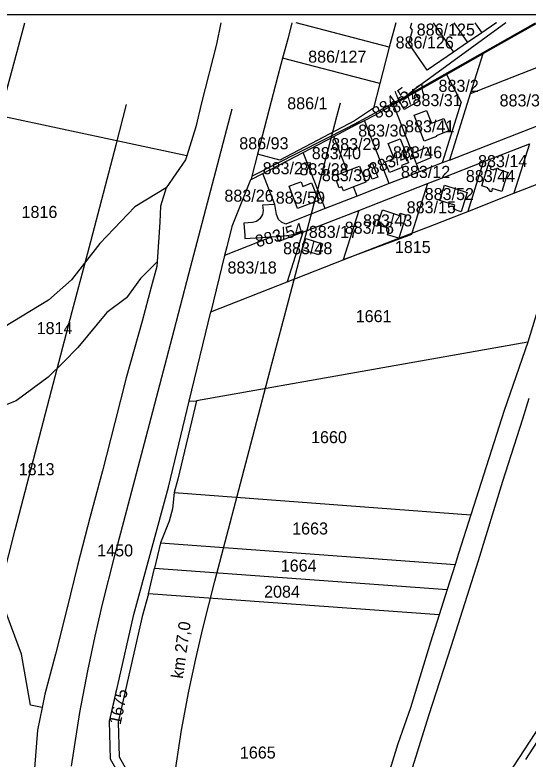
# Model space of a CAD drawing. Extents: x -583889 to -582839, y -1166553 to -1165068.
# Drawn here: x -583410.2 to -583111.8, y -1165500.8 to -1165067.8 of the extents above; entities that cross this region are included whole.
import ezdxf

# ---------------------------------------------------------------- set-up
doc = ezdxf.new("R2010")
doc.units = 0
for name, color, linetype in [('37', 7, 'Continuous'), ('_parcely přehledka', 7, 'Continuous'), ('Hranice parcel', 7, 'Continuous'), ('Parcelní čísla', 7, 'Continuous')]:
    doc.layers.add(name, color=color, linetype=linetype)

msp = doc.modelspace()

# ---------------------------------------------------------------- linework, layer by layer
at = {"layer": '37'}
for points in [[(-583417.44, -1165396.54), (-583410.09, -1165367.4), (-583389.99, -1165290.81), (-583376.8, -1165240.45), (-583367.04, -1165203.24), (-583351.37, -1165143.48), (-583345.2, -1165119.98)], [(-583317.86, -1165513.43), (-583313.23, -1165483.92), (-583308.97, -1165461.26), (-583304.95, -1165442.46), (-583300.84, -1165424.92), (-583293.87, -1165397.32), (-583273.91, -1165321.23), (-583260.72, -1165270.87), (-583250.96, -1165233.68), (-583235.29, -1165173.92), (-583222.96, -1165126.91), (-583220.86, -1165118.88)], [(-583377.27, -1165504.99), (-583372.36, -1165473.73), (-583367.8, -1165449.45), (-583363.5, -1165429.34), (-583359.14, -1165410.73), (-583351.98, -1165382.36), (-583344.08, -1165352.25), (-583331.95, -1165306.02), (-583318.76, -1165255.66), (-583309, -1165218.46), (-583293.33, -1165158.7), (-583283.82, -1165122.45)]]:
    msp.add_lwpolyline(points, dxfattribs=at)
at = {"layer": '_parcely přehledka'}
msp.add_lwpolyline([(-583888.67, -1166552.78), (-582838.67, -1166552.78), (-582838.67, -1165067.78), (-583888.67, -1165067.78), (-583888.67, -1166552.78)], dxfattribs=at)
at = {"layer": 'Hranice parcel'}
for p, q in [((-583192.52, -1165086.48), (-583246.64, -1165072.33)), ((-583188.82, -1165072.33), (-583192.52, -1165086.48)), ((-583182.09, -1165114.62), (-583107.53, -1165072.33)), ((-583167.06, -1165072.33), (-583155.29, -1165089.5)), ((-583154.94, -1165072.33), (-583147.04, -1165083.85)), ((-583142.81, -1165072.33), (-583138.79, -1165078.2)), ((-583130.54, -1165072.55), (-583138.79, -1165078.2)), ((-583106.15, -1165072.33), (-583138.25, -1165090.53)), ((-583130.69, -1165072.33), (-583130.54, -1165072.55)), ((-583130.22, -1165072.33), (-583130.54, -1165072.55)), ((-583138.79, -1165078.2), (-583147.04, -1165083.85)), ((-583060.04, -1165080.27), (-583145.52, -1165113.73)), ((-583147.04, -1165083.85), (-583155.29, -1165089.5)), ((-583192.52, -1165086.48), (-583198.08, -1165107.77)), ((-583198.08, -1165107.77), (-583254.56, -1165093)), ((-583159.2, -1165102.41), (-583138.25, -1165090.53)), ((-583138.25, -1165090.53), (-583145.52, -1165113.73)), ((-583177.74, -1165112.93), (-583159.2, -1165102.41)), ((-583209.97, -1165129.86), (-583182.09, -1165114.62)), ((-583185.39, -1165117.27), (-583177.74, -1165112.93)), ((-583182.09, -1165114.62), (-583185.39, -1165117.27)), ((-583145.52, -1165113.73), (-583157.61, -1165152.25)), ((-583190.15, -1165119.97), (-583186.69, -1165118.01)), ((-583179.13, -1165148.17), (-583190.15, -1165119.97)), ((-583186.69, -1165118.01), (-583185.39, -1165117.27)), ((-583157.61, -1165152.25), (-583071.94, -1165118.73)), ((-583310.2, -1165149.72), (-583419.03, -1165126.58)), ((-583213.82, -1165132.82), (-583206.95, -1165129.23)), ((-583192.59, -1165165.93), (-583206.95, -1165129.23)), ((-583224.78, -1165138.54), (-583213.82, -1165132.82)), ((-583213.82, -1165132.82), (-583209.97, -1165129.86)), ((-583242.61, -1165147.85), (-583224.78, -1165138.54)), ((-583216.94, -1165158.58), (-583224.78, -1165138.54)), ((-583137.89, -1165153.24), (-583111.02, -1165142.73)), ((-583111.02, -1165142.73), (-583120.08, -1165171.59)), ((-583269.11, -1165148.86), (-583272.42, -1165161.67)), ((-583266.01, -1165160.07), (-583242.61, -1165147.85)), ((-583229.84, -1165180.5), (-583242.61, -1165147.85)), ((-583176.72, -1165154.36), (-583179.13, -1165148.17)), ((-583174.9, -1165159.01), (-583176.72, -1165154.36)), ((-583161.79, -1165153.89), (-583174.9, -1165159.01)), ((-583157.61, -1165152.25), (-583161.79, -1165153.89)), ((-583137.89, -1165153.24), (-583146.95, -1165182.1)), ((-583174.9, -1165159.01), (-583192.59, -1165165.93)), ((-583120.08, -1165171.59), (-583084.11, -1165157.51)), ((-583273.25, -1165163.85), (-583266.01, -1165160.07)), ((-583258.98, -1165178.07), (-583266.01, -1165160.07)), ((-583211.22, -1165173.22), (-583213.34, -1165167.8)), ((-583192.59, -1165165.93), (-583211.22, -1165173.22)), ((-583210.23, -1165181.54), (-583170.28, -1165165.91)), ((-583170.28, -1165165.91), (-583179.34, -1165194.77)), ((-583146.95, -1165182.1), (-583120.08, -1165171.59)), ((-583211.22, -1165173.22), (-583229.84, -1165180.5)), ((-583242.78, -1165194.27), (-583210.23, -1165181.54)), ((-583210.23, -1165181.54), (-583219.29, -1165210.4)), ((-583242.78, -1165194.27), (-583251.84, -1165223.13)), ((-583260.77, -1165196.96), (-583288.23, -1165207.7)), ((-583260.77, -1165196.96), (-583257.89, -1165196.79)), ((-583288.23, -1165207.7), (-583296.29, -1165240.52)), ((-583251.84, -1165223.13), (-583219.29, -1165210.4)), ((-583296.29, -1165240.52), (-583251.84, -1165223.13)), ((-583308.83, -1165292.52), (-583296.29, -1165240.52)), ((-583112.09, -1165258.27), (-583304.62, -1165292.26)), ((-583308.83, -1165292.52), (-583304.62, -1165292.26)), ((-583317.66, -1165345.79), (-583145.07, -1165358.62)), ((-583325.5, -1165374.92), (-583329.03, -1165389.78)), ((-583325.5, -1165374.92), (-583154.3, -1165387.67)), ((-583154.3, -1165387.67), (-583158.9, -1165402.17)), ((-583332.55, -1165404.6), (-583329.03, -1165389.78)), ((-583329.03, -1165389.78), (-583158.9, -1165402.17)), ((-583158.9, -1165402.17), (-583163.57, -1165416.9)), ((-583163.57, -1165416.9), (-583332.55, -1165404.6))]:
    msp.add_line(p, q, dxfattribs=at)
for points in [[(-583419.03, -1165126.58), (-583408.09, -1165086.08), (-583404.38, -1165072.33)], [(-583290.39, -1165072.33), (-583293.05, -1165084.81), (-583301.65, -1165118.91), (-583304.95, -1165132.91), (-583310.2, -1165149.72)], [(-583249.12, -1165072.33), (-583251.38, -1165081.18), (-583254.56, -1165093)], [(-583124.73, -1165072.33), (-583177.59, -1165111.01), (-583182.09, -1165114.62)], [(-583155.29, -1165089.5), (-583170.56, -1165099.96), (-583181.14, -1165084.5), (-583179.11, -1165076.73), (-583180.24, -1165075.09), (-583179.52, -1165072.33)], [(-583254.56, -1165093), (-583257.31, -1165103.21), (-583269.11, -1165148.86)], [(-583159.2, -1165102.41), (-583150.74, -1165118.66), (-583161.79, -1165153.89)], [(-583198.08, -1165107.77), (-583201.79, -1165121.97), (-583212.74, -1165129.47), (-583256.06, -1165152.27), (-583269.11, -1165148.86)], [(-583177.74, -1165112.93), (-583174.94, -1165117.84), (-583183.93, -1165122.9), (-583186.69, -1165118.01)], [(-583206.95, -1165129.23), (-583201, -1165126.12), (-583190.15, -1165119.97)], [(-583178.04, -1165126.19), (-583170.85, -1165123.38), (-583167.95, -1165130.86), (-583160.8, -1165128.06), (-583158.01, -1165135.2), (-583165.21, -1165138.06), (-583165.03, -1165138.53), (-583172.2, -1165141.29), (-583178.04, -1165126.19)], [(-583272.42, -1165161.67), (-583216.55, -1165133.21), (-583209.97, -1165129.86)], [(-583194.84, -1165153.37), (-583189.72, -1165151.36), (-583193.17, -1165142.57), (-583186.16, -1165139.84), (-583182.54, -1165149.06), (-583183.1, -1165149.27), (-583181.31, -1165153.85), (-583185.41, -1165155.45), (-583184.97, -1165156.57), (-583192.44, -1165159.48), (-583194.84, -1165153.37)], [(-583179.13, -1165148.17), (-583170.78, -1165144.83), (-583168.3, -1165151), (-583176.72, -1165154.36)], [(-583310.2, -1165149.72), (-583310.93, -1165152.06), (-583322.15, -1165168.47)], [(-583202.27, -1165154.28), (-583199.18, -1165162.12), (-583202.45, -1165163.41), (-583204.81, -1165157.44), (-583203.78, -1165157.04), (-583204.52, -1165155.17), (-583202.27, -1165154.28)], [(-583170.28, -1165165.91), (-583160.72, -1165162.17), (-583137.89, -1165153.24)], [(-583135.17, -1165168.49), (-583138.74, -1165167.33), (-583135, -1165155.19), (-583133.37, -1165155.73), (-583133.88, -1165157.4), (-583131.93, -1165157.97), (-583131.75, -1165157.37), (-583130.94, -1165157.65), (-583130.79, -1165157.12), (-583129.97, -1165157.39), (-583129.81, -1165156.86), (-583128.97, -1165157.1), (-583129.16, -1165157.64), (-583124.03, -1165159.23), (-583123.33, -1165159.47), (-583123.47, -1165159.94), (-583123.86, -1165159.84), (-583127.2, -1165170.5), (-583132.64, -1165168.78), (-583133.2, -1165170.78), (-583134.02, -1165170.52), (-583133.86, -1165170.02), (-583134.66, -1165169.74), (-583134.5, -1165169.23), (-583135.31, -1165168.95), (-583135.17, -1165168.49)], [(-583213.34, -1165167.8), (-583219.24, -1165170.11), (-583220.15, -1165167.79), (-583221.58, -1165168.36), (-583223.16, -1165164.33), (-583221.71, -1165163.77), (-583222.84, -1165160.89), (-583216.94, -1165158.58)], [(-583216.94, -1165158.58), (-583209.83, -1165155.79), (-583206.23, -1165165.02), (-583213.34, -1165167.8)], [(-583273.25, -1165163.85), (-583284.11, -1165190.92), (-583286.96, -1165202.76), (-583288.23, -1165207.7)], [(-583272.42, -1165161.67), (-583272.88, -1165163.39), (-583273.25, -1165163.85)], [(-583250.8, -1165167.53), (-583246.62, -1165165.93), (-583243.85, -1165164.96), (-583242.84, -1165167.68), (-583237.68, -1165165.6), (-583233.77, -1165175.77), (-583245.84, -1165180.42), (-583250.8, -1165167.53)], [(-583154.41, -1165178.52), (-583163.24, -1165175.74), (-583160.51, -1165166.95), (-583147.19, -1165171.14), (-583150.71, -1165182.29), (-583155.13, -1165180.9), (-583154.41, -1165178.52)], [(-583322.15, -1165168.47), (-583340.5, -1165179.46), (-583360.81, -1165200.75), (-583377.25, -1165221.89), (-583390.68, -1165233.74), (-583416.76, -1165249.61), (-583440.61, -1165276.22), (-583445.47, -1165291.1), (-583456.44, -1165295.04)], [(-583322.15, -1165168.47), (-583325.57, -1165179.12), (-583326, -1165188.3), (-583327.43, -1165211.57)], [(-583258.98, -1165178.07), (-583266.29, -1165178.5), (-583265.88, -1165181.52), (-583266.18, -1165183.96), (-583267.73, -1165186.48), (-583269.73, -1165187.92), (-583272.1, -1165188.61), (-583277.05, -1165188.92), (-583276.57, -1165196.2), (-583276.47, -1165197.91), (-583260.77, -1165196.96)], [(-583229.84, -1165180.5), (-583248.47, -1165187.79), (-583252.75, -1165189.46), (-583255.2, -1165188.46), (-583256.97, -1165186.76), (-583258.07, -1165184), (-583258.98, -1165178.07)], [(-583186.95, -1165197.75), (-583193.56, -1165195.75), (-583192.62, -1165192.82), (-583193.18, -1165191.92), (-583199.34, -1165189.93), (-583196.55, -1165181.19), (-583186.6, -1165184.42), (-583186.22, -1165183.15), (-583182.66, -1165184.28), (-583186.95, -1165197.75)], [(-583179.34, -1165194.77), (-583169.78, -1165191.03), (-583146.95, -1165182.1)], [(-583257.89, -1165196.79), (-583257.11, -1165196.74), (-583252.11, -1165196.21), (-583249.62, -1165195.75), (-583242.78, -1165194.27)], [(-583242.78, -1165194.27), (-583256.75, -1165199.73), (-583257.89, -1165196.79)], [(-583241.02, -1165197.83), (-583231.44, -1165200.93), (-583233.47, -1165207.47), (-583243.14, -1165204.44), (-583241.02, -1165197.83)], [(-583219.29, -1165210.4), (-583186.95, -1165197.75), (-583179.34, -1165194.77)], [(-583179.34, -1165194.77), (-583179.66, -1165195.53), (-583219.29, -1165210.4)], [(-583327.43, -1165211.57), (-583337.15, -1165221.16), (-583345.28, -1165232.38), (-583356.63, -1165240.96), (-583373.5, -1165261.36), (-583381.99, -1165269.78), (-583390.9, -1165278.52), (-583409.51, -1165292.26), (-583429.18, -1165300.2), (-583454.83, -1165307.19)], [(-583327.43, -1165211.57), (-583327.59, -1165214.21), (-583330.92, -1165226.21), (-583336.19, -1165245.95), (-583345.5, -1165278.93), (-583352.15, -1165304.95), (-583359.3, -1165333.07), (-583366.57, -1165360.34), (-583373.53, -1165387.37), (-583380.03, -1165413.66), (-583386.52, -1165439.72), (-583392.75, -1165463.03), (-583394.35, -1165470.85)], [(-583097.01, -1165208.5), (-583101.24, -1165222.44), (-583112.09, -1165258.27)], [(-583112.09, -1165258.27), (-583125.85, -1165297.89), (-583145.07, -1165358.62)], [(-583361.04, -1165570.69), (-583342.57, -1165547.76), (-583341.85, -1165530.97), (-583343.72, -1165519.91), (-583354.54, -1165500.86), (-583355.11, -1165478.77), (-583350.44, -1165458.56), (-583341.01, -1165416.67), (-583320.9, -1165342.6), (-583308.83, -1165292.52)], [(-583304.62, -1165292.26), (-583315.52, -1165337.89), (-583317.66, -1165345.79)], [(-583184.72, -1165523.62), (-583182.81, -1165517.68), (-583176.05, -1165496.65), (-583169.59, -1165475.46), (-583156.46, -1165434.65), (-583140.6, -1165385.28), (-583126.45, -1165339.09), (-583115, -1165302.85), (-583111.16, -1165290.82)], [(-583394.35, -1165470.85), (-583401.02, -1165469.37), (-583406.34, -1165439.81), (-583441.73, -1165344.5), (-583443.26, -1165334.4), (-583448.82, -1165319.07), (-583454.83, -1165307.19)], [(-583150.03, -1165547.02), (-583146.45, -1165545.26), (-583081.48, -1165445.65), (-583060.78, -1165413.9), (-582999.79, -1165321.21), (-583000.42, -1165318.79)], [(-583317.66, -1165345.79), (-583318.57, -1165355.26), (-583320.51, -1165362.38), (-583325.5, -1165374.92)], [(-583145.07, -1165358.62), (-583152.23, -1165381.21), (-583154.3, -1165387.67)], [(-583332.55, -1165404.6), (-583336.16, -1165417.88), (-583350.1, -1165479.27), (-583349.57, -1165499.48), (-583339.8, -1165516.68), (-583336.86, -1165530.49), (-583338.68, -1165550.89), (-583347.2, -1165561.47), (-583348.01, -1165573.19)], [(-583163.57, -1165416.9), (-583168.61, -1165432.78), (-583180.14, -1165470.95), (-583187.62, -1165491.96), (-583193.05, -1165509.63), (-583194.86, -1165515.1)], [(-583078.55, -1165447.56), (-583104.44, -1165487.27), (-583113.44, -1165501.07)], [(-583394.35, -1165470.85), (-583397.05, -1165483.9), (-583399.8, -1165518.65), (-583400, -1165542.33), (-583402.51, -1165559.81), (-583402.19, -1165563.54), (-583409.42, -1165564.02), (-583405.3, -1165586.77), (-583405.42, -1165638.41)]]:
    msp.add_lwpolyline(points, dxfattribs=at)

# ---------------------------------------------------------------- texts
msp.add_text('km 27,0', height=7, rotation=82.0212).set_placement((-583312.5, -1165454.26))
at = {"layer": 'Parcelní čísla'}
for s, p in [('886/125', (-583176.6, -1165079.83)), ('886/126', (-583188.85, -1165087.31)), ('886/127', (-583239.68, -1165095.58)), ('883/2', (-583163.92, -1165112.56)), ('886/1', (-583251.86, -1165122.73)), ('883/31', (-583179.05, -1165120.88)), ('883/3', (-583128.41, -1165121.04)), ('883/41', (-583183.35, -1165136.11)), ('883/30', (-583210.6, -1165138.6)), ('886/93', (-583279.73, -1165145.99)), ('883/29', (-583226.29, -1165146.48)), ('883/40', (-583237.59, -1165151.74)), ('883/46', (-583190.4, -1165151.24)), ('883/14', (-583140.94, -1165156.38)), ('883/27', (-583266.13, -1165160.49)), ('883/28', (-583244.77, -1165161.09)), ('883/12', (-583185.74, -1165162.64)), ('883/39', (-583231.71, -1165164.56)), ('883/44', (-583148.02, -1165165.05)), ('883/52', (-583171.94, -1165175.53)), ('883/26', (-583288.38, -1165176.48)), ('883/59', (-583258.52, -1165177.63)), ('883/15', (-583182.42, -1165183.23)), ('1816', (-583406.3, -1165185.94)), ('883/43', (-583207.79, -1165190.86)), ('883/16', (-583218.44, -1165195.14)), ('883/17', (-583239.32, -1165197.53)), ('883/48', (-583254.26, -1165207.05)), ('1815', (-583189.29, -1165206.35)), ('883/18', (-583286.58, -1165218.29)), ('1661', (-583212.05, -1165246.58)), ('1814', (-583397.49, -1165253.55)), ('1660', (-583238.01, -1165316.98)), ('1813', (-583407.93, -1165335.62)), ('1663', (-583248.99, -1165370.14)), ('1450', (-583362.28, -1165382.89)), ('1664', (-583255.63, -1165391.72)), ('2084', (-583265.32, -1165406.91)), ('1665', (-583279.38, -1165500.5))]:
    msp.add_text(s, height=7, dxfattribs=at).set_placement(p)
for s, rotation, p in [('883/47', 32, (-583193.77, -1165128.32)), ('884/5', 36, (-583199.35, -1165128.61)), ('883/42', 22, (-583202.48, -1165161.15)), ('883/54', 16, (-583269.24, -1165203.13)), ('1675', 78, (-583348.76, -1165481.23))]:
    msp.add_text(s, height=7, rotation=rotation, dxfattribs=at).set_placement(p)

doc.saveas('drawing.dxf')
